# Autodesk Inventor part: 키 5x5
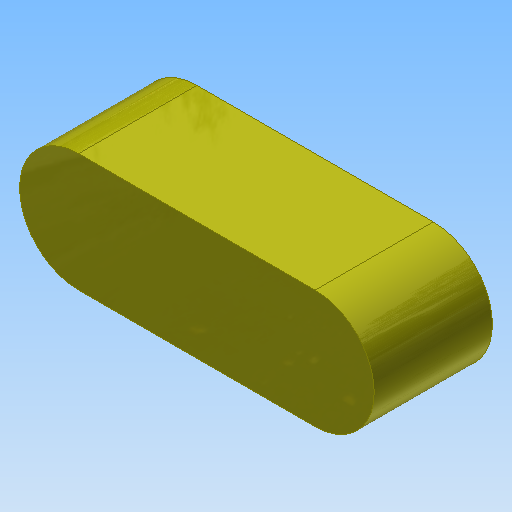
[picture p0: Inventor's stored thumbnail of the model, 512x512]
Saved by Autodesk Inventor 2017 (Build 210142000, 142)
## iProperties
Created: 2011-04
Part Number: 키 5x5
Document SubType Name: Modeling
Designer: pww
Density: 7.86 g/cm^3
Material: 강철, 연강
Appearance: 노란색
Author: pww
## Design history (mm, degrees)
sketch "스케치1"
  geometry: L1 (-5, -2.5)-(5, -2.5); L2 (5, 2.5)-(-5, 2.5); A1 r 2.5 centre (-5, 0) between (-5, 2.5) and (-5, -2.5); A2 r 2.5 centre (5, 0) between (5, -2.5) and (5, 2.5); 1 further point
  constraints: 4 end point, 4 point on circle, 2 centre point
extrude "돌출1" new body sketch "스케치1" distance "d0" = 5; taper "d1" = 0 deg
node "솔리드1"
